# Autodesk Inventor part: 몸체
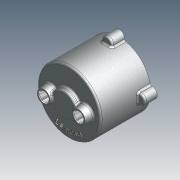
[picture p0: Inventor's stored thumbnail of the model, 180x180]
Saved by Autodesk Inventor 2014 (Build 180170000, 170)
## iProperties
Company: 한국ATC센터
Created: 2012-05
Part Number: 몸체
Document SubType Name: 모델링
Designer: KYOUNG IL JANG
Mass: 471.041 g
Surface Area: 679.307 cm^2
Volume: 173.816 cm^3
Density: 2.71 g/cm^3
Material: 알루미늄-6061
Appearance: 알루미늄 - 평지
변환 표준: STEP AP214IS
파일 이름: C:\Users\SeoGD\Desktop\?쒗뿕\紐몄껜.stp
전처리기: Build: 253, Release: 2010 SP1 - Date: Wed 07/29/2009
전송 단위: 밀리미터
불확실성: 0.01
Author: KYOUNG IL JANG
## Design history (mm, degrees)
sketch "스케치2"
  geometry: C1 r 50 at (0, 0); 1 further point
  constraints: 1 centre point, 1 coincident
  dimensions: "d9" = 100 diameter of C1
extrude "돌출2" new body sketch "스케치2" distance "d10" = 80; taper "d11" = 0 deg
feature "쉘1" dims "d12" = 5
sketch "스케치3" dims "d13" = 55
  geometry: C1 r 7.5 at (27.5, 0); C2 r 12.5 at (27.5, 0); 2 further points
  constraints: 2 centre point, 2 coincident, 2 horizontal alignment, 2 other
  dimensions: "d14" = 15 diameter of C1; "d15" = 25 diameter of C2
extrude "돌출3" join sketch "스케치3" distance "d16" = 12; taper "d17" = -10 deg
hole "구멍2" diameter "d20" = 15; stored, may be unused: countersink angle "d24" = 90 deg, drill point angle "d26" = 118 deg; dims "d18" = 10, "d19" = 10, "d21" = 6, "d22" = 4, "d23" = 2, "d25" = 15
chamfer "모따기1" distance "d27" = 1; stored, may be unused: second distance "d28" = 2, angle "d29" = 45 deg
sketch "스케치4"
  geometry: L1 (0, 0)-(0, 88); L2 (0, 70)-(13.16, 70); L3 (-45, 75)-(45, 75) reference; L4 (-50, 80)-(50, 80) reference; L5 (13.16, 70)-(14.5, 75); L6 (20, 80)-(20, 88); L7 (20, 88)-(0, 88); L8 (20, 80)-(14.5, 75)
  constraints: 12 end point, 3 point on line, 2 perpendicular, 1 vertical
  dimensions: "d34" = 40 diameter of L6 L1; "d35" = 105 deg angle of L5 L3; "d36" = 5 distance between parallel lines of L2 L3; "d37" = 8 distance between parallel lines of L7 L4; "d51" = 29 diameter of L5.end L1
revolve "회전1" sketch "스케치4" stored, may be unused: angle "d38" = 90 deg
hole "구멍3" diameter "d41" = 15; stored, may be unused: countersink angle "d45" = 90 deg, drill point angle "d47" = 0 deg; dims "d39" = 10, "d40" = 10, "d42" = 6, "d43" = 22, "d44" = 13, "d46" = 15
chamfer "모따기2" distance "d48" = 1; stored, may be unused: second distance "d49" = 2, angle "d50" = 45 deg
fillet "모깎기1" dims "d52" = 3
fillet "모깎기2" dims "d53" = 3, "d72" = 0.2
sketch "스케치5"
  geometry: A1 r 50 centre (0, 0) between (50, 0) and (-8.074, 49.344) reference; A2 r 8.5 centre (0, 52) between (8.074, 49.344) and (-8.074, 49.344); 1 further point
  constraints: 5 point on circle, 1 centre point, 1 horizontal alignment
  dimensions: "d54" = 90 deg dimension on point (0, 0) A2.centre A1.start; "d55" = 52 distance of A2.centre point (0, 0); "d56" = 17 diameter of A2
extrude "돌출4" join sketch "스케치5" distance "d57" = 20; taper "d58" = 0 deg
fillet "모깎기3" dims "d59" = 3
hole "구멍4" diameter "d62" = 4.134; stored, may be unused: countersink angle "d66" = 90 deg, drill point angle "d68" = 118 deg; dims "d60" = 10, "d61" = 10, "d63" = 12, "d64" = 22, "d65" = 13, "d67" = 15
sketch "스케치6"
  geometry: C1 r 47 at (0, 0) reference; C2 r 42.5 at (0, 0); 1 further point
  constraints: 1 centre point, 1 coincident, 1 other
  dimensions: "d73" = 85 diameter of C2
feature "엠보싱1" sketch "스케치6" dims "d74" = 1, "d75" = 0
node "솔리드1"
node "솔리드 본체"
node "곡면 본체"
pattern_circular "원형 패턴1" dims "d31" = 360 deg
pattern_circular "원형 패턴2" dims "d70" = 360 deg
node "솔리드2"
